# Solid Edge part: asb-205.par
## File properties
Author: nakano
Template: iso metric part.par
Last saved by: nakano
Revision: 3
Application: Solid Edge
Density: 2772.04254170526 kg/m^3
Accuracy: 0.990
Username: nakano
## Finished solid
Body 1: solid body, 65 faces, 146 edges, 72 vertices.
  Faces by surface: plane 36, cylinder 29
  Edges by curve: line 88, circle 58
Bounding box of the edges (mm): 76.987 x 31.750 x 88.900, from (-38.4937, -15.875, 0) to (38.4937, 15.875, 88.9).
Cylindrical faces by radius (mm): R0.8128 x4, R1.1938 x8, R1.5875 x8, R2.3368 x4, R4.0005 x2, R4.7498 x1, R12.3063 x1, R15.875 x1
Planar faces by outward normal: +x 2, +y 11, +z 3, -x 2, -y 11, -z 3, oblique 4
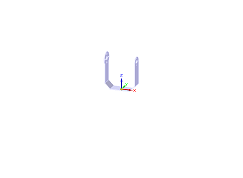
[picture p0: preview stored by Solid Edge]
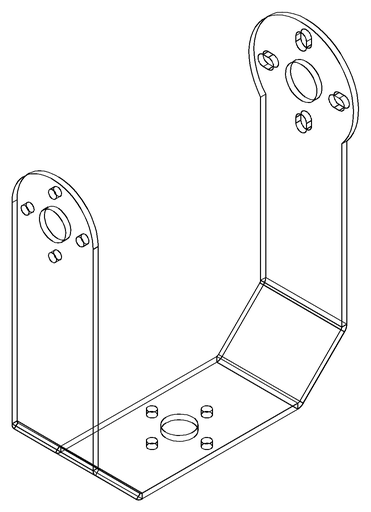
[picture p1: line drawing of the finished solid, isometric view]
